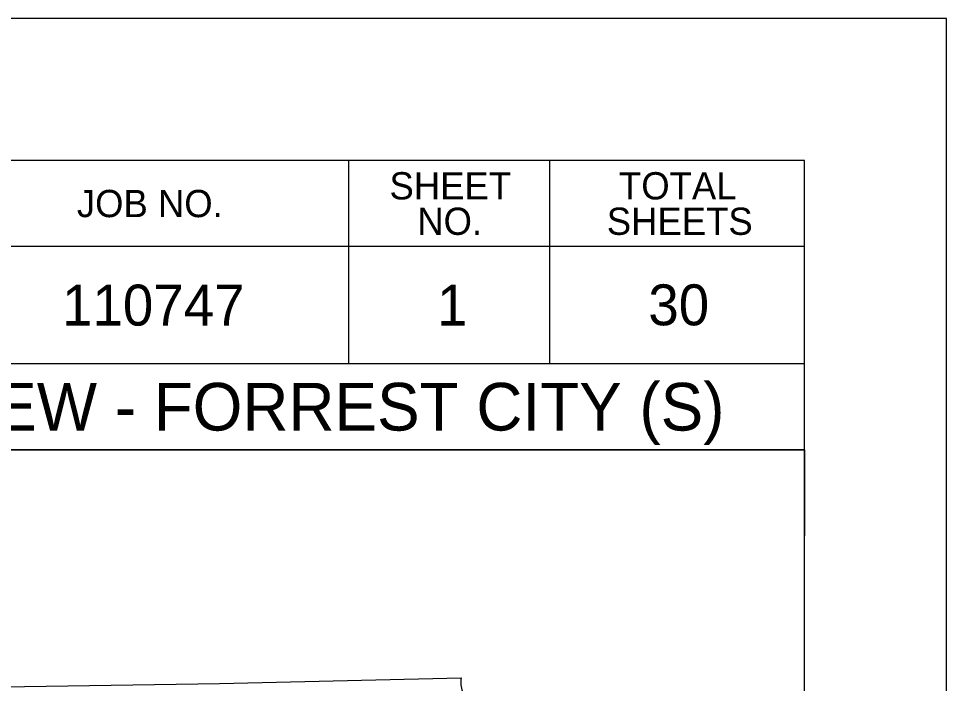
# Model space of a CAD drawing. Extents: x -0.96 to 2.36, y -0.12 to 0.92.
# Drawn here: x 1.2805 to 1.4167, y 0.8191 to 0.9167 of the extents above; entities that cross this region are included whole.
import ezdxf

# ---------------------------------------------------------------- set-up
doc = ezdxf.new("R2010")
doc.units = 0
for name, color, linetype in [('SHET_Annotations', 7, 'Continuous'), ('SHET_Border-Lines', 7, 'Continuous'), ('SHET_Border-Text', 7, 'Continuous')]:
    doc.layers.add(name, color=color, linetype=linetype)

msp = doc.modelspace()

# ---------------------------------------------------------------- linework, layer by layer
at = {"layer": 'SHET_Annotations'}
msp.add_lwpolyline([(1.0951, 0.81784), (1.16886, 0.81779), (1.23364, 0.81792), (1.31002, 0.81908), (1.34545, 0.81991)], dxfattribs=at)
msp.add_spline([(1.34545, 0.81991), (1.34568, 0.81792), (1.3463, 0.81688), (1.34641, 0.81496), (1.34718, 0.81413), (1.34851, 0.81333), (1.34967, 0.81198), (1.34993, 0.81042), (1.34957, 0.80884), (1.34949, 0.80708), (1.34931, 0.80552), (1.34905, 0.80409), (1.34794, 0.80295), (1.3469, 0.80215), (1.34594, 0.80119), (1.34526, 0.80015), (1.34405, 0.79906), (1.34288, 0.79792), (1.34192, 0.79691), (1.34099, 0.79564), (1.34049, 0.79424), (1.33948, 0.79323), (1.33865, 0.79232), (1.33754, 0.7911), (1.33699, 0.78983), (1.33595, 0.78846), (1.33569, 0.78708), (1.33448, 0.78431)], degree=3, dxfattribs=at)
at = {"layer": 'SHET_Border-Lines'}
for p, q in [((1.32894, 0.89583), (1.32894, 0.86601)), ((1.35843, 0.89583), (1.35843, 0.86601)), ((1.39583, 0.8832), (1.21266, 0.8832)), ((1.39583, 0.88328), (1.39583, 0.88328)), ((1.39583, 0.86601), (1.21266, 0.86601)), ((1.39583, 0.85338), (1.21266, 0.85338))]:
    msp.add_line(p, q, dxfattribs=at)
for points in [[(0, 0), (1.41666, 0), (1.41666, 0.91666), (0, 0.91666)], [(0.04167, 0.02083), (1.39583, 0.02083), (1.39583, 0.89583), (0.04167, 0.89583)]]:
    msp.add_lwpolyline(points, close=True, dxfattribs=at)
msp.add_lwpolyline([(1.12962, 0.85338), (1.21266, 0.85338), (1.39583, 0.85338), (1.39583, 0.84075), (1.39583, 0.89583), (1.12962, 0.89583)], dxfattribs=at)

# ---------------------------------------------------------------- texts
at = {"layer": 'SHET_Annotations'}
for s, height, p in [('110747', 0.006, (1.28692, 0.87161)), ('1', 0.006, (1.34194, 0.87161)), ('30', 0.006, (1.37293, 0.87165)), ('BAYOU DEVIEW - FORREST CITY (S)', 0.007, (1.21976, 0.8562))]:
    msp.add_text(s, height=height, dxfattribs=at).set_placement(p)
at = {"layer": 'SHET_Border-Text'}
for s, p in [('SHEET', (1.33496, 0.89012)), ('TOTAL', (1.36863, 0.89012)), ('JOB NO.', (1.2891, 0.88752)), ('NO.', (1.33903, 0.88492)), ('SHEETS', (1.36684, 0.88492))]:
    msp.add_text(s, height=0.004, dxfattribs=at).set_placement(p)

doc.saveas('drawing.dxf')
